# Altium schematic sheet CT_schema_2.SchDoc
size 307 x 173 mm
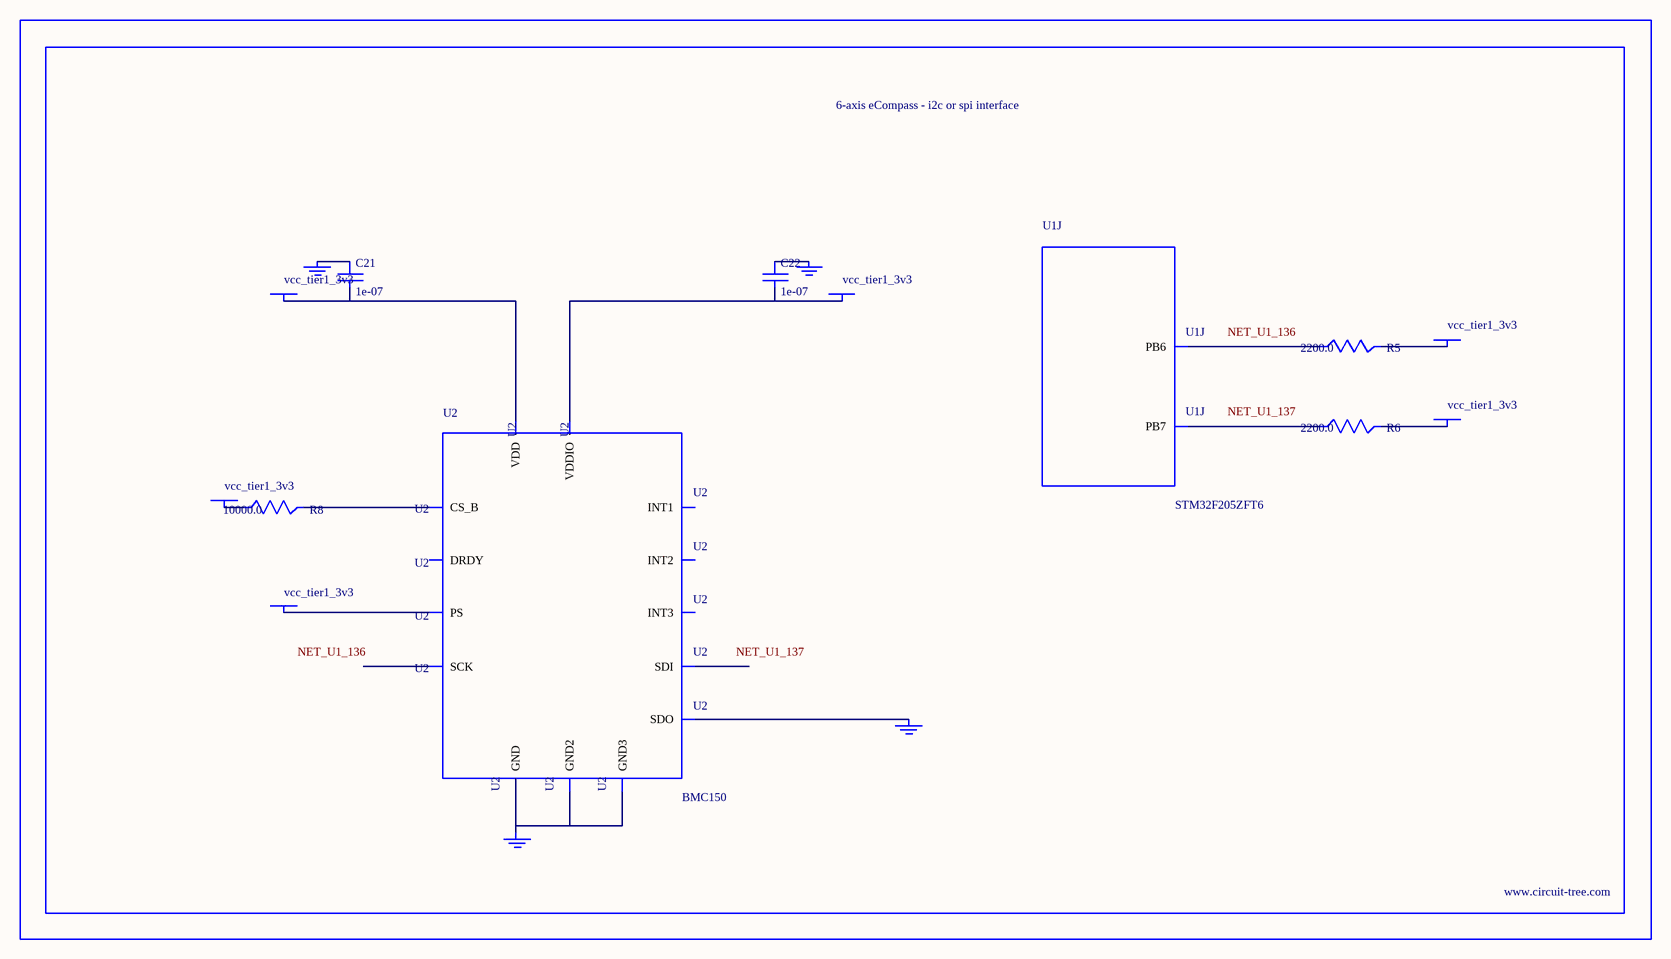
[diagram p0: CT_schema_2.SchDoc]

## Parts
BORDER1  (no value)
C21  1e-07  [C0402]
C22  1e-07  [C0402]
GND_INSTANCE_1_0  (no value)
GND_INSTANCE_1_1  (no value)
GND_INSTANCE_1_2  (no value)
GND_INSTANCE_1_3  (no value)
POWER_INSTANCE_1_0  vcc_tier1_3v3
POWER_INSTANCE_1_1  vcc_tier1_3v3
POWER_INSTANCE_1_2  vcc_tier1_3v3
POWER_INSTANCE_1_3  vcc_tier1_3v3
POWER_INSTANCE_1_4  vcc_tier1_3v3
POWER_INSTANCE_1_5  vcc_tier1_3v3
R5  2200.0  [R0603]
R6  2200.0  [R0603]
R8  10000.0  [R0603]
U1  STM32F205ZFT6  [LQFP144]  (part J of 13)
U2  BMC150  [LGA14R35P5X6_200X200X100]

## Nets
NetC21_1: C21.1 GND_INSTANCE_1_1.0(GND)
NetC21_2: C21.2 POWER_INSTANCE_1_0.0(PWR) U2.8(VDD)
NetC22_1: C22.1 GND_INSTANCE_1_2.0(GND)
NetC22_2: C22.2 POWER_INSTANCE_1_1.0(PWR) U2.10(VDDIO)
NetGND_INSTANCE_1_0_0: GND_INSTANCE_1_0.0(GND) U2.1(SDO)
NetGND_INSTANCE_1_3_0: GND_INSTANCE_1_3.0(GND) U2.6(GND) U2.7(GND2) U2.9(GND3)
NetPOWER_INSTANCE_1_2_0: POWER_INSTANCE_1_2.0(PWR) R8.1
NetPOWER_INSTANCE_1_3_0: POWER_INSTANCE_1_3.0(PWR) U2.13(PS)
NetPOWER_INSTANCE_1_4_0: POWER_INSTANCE_1_4.0(PWR) R5.2
NetPOWER_INSTANCE_1_5_0: POWER_INSTANCE_1_5.0(PWR) R6.2
NetR5_1: R5.1 U1.136(PB6)
NetR6_1: R6.1 U1.137(PB7)
NetR8_2: R8.2 U2.12(CS_B)

Not connected (* = marked no-connect by the designer): U2 2(INT1) 3(INT2) 4(DRDY) 5(INT3) 11(SCK) 14(SDI)

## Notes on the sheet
- Labels drawn without touching a wire or pin: NET_U1_136, NET_U1_137

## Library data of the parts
BORDER1 = BORDER_PAGE1
C21 C22 = C0402C104K3RACTU
GND_INSTANCE_1_0-GND_INSTANCE_1_3 = GND
POWER_INSTANCE_1_0-POWER_INSTANCE_1_5 = PWR
R5 R6 = RC0603JR-072K2L
R8 = RC0603JR-0710KL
